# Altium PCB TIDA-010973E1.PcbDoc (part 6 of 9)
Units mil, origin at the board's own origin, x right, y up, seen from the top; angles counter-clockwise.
Board outline 5166 x 3669 mil, 8 copper layers (L01 - TOP, L02 - GND, L03 - SIG, L04 - GND, L05 - PWR, L06 - SIG, L07 - GND, L08 - BOTTOM), stack 61.7 mil thick; 677 components, 493 nets, 2522 pads, 1424 vias.
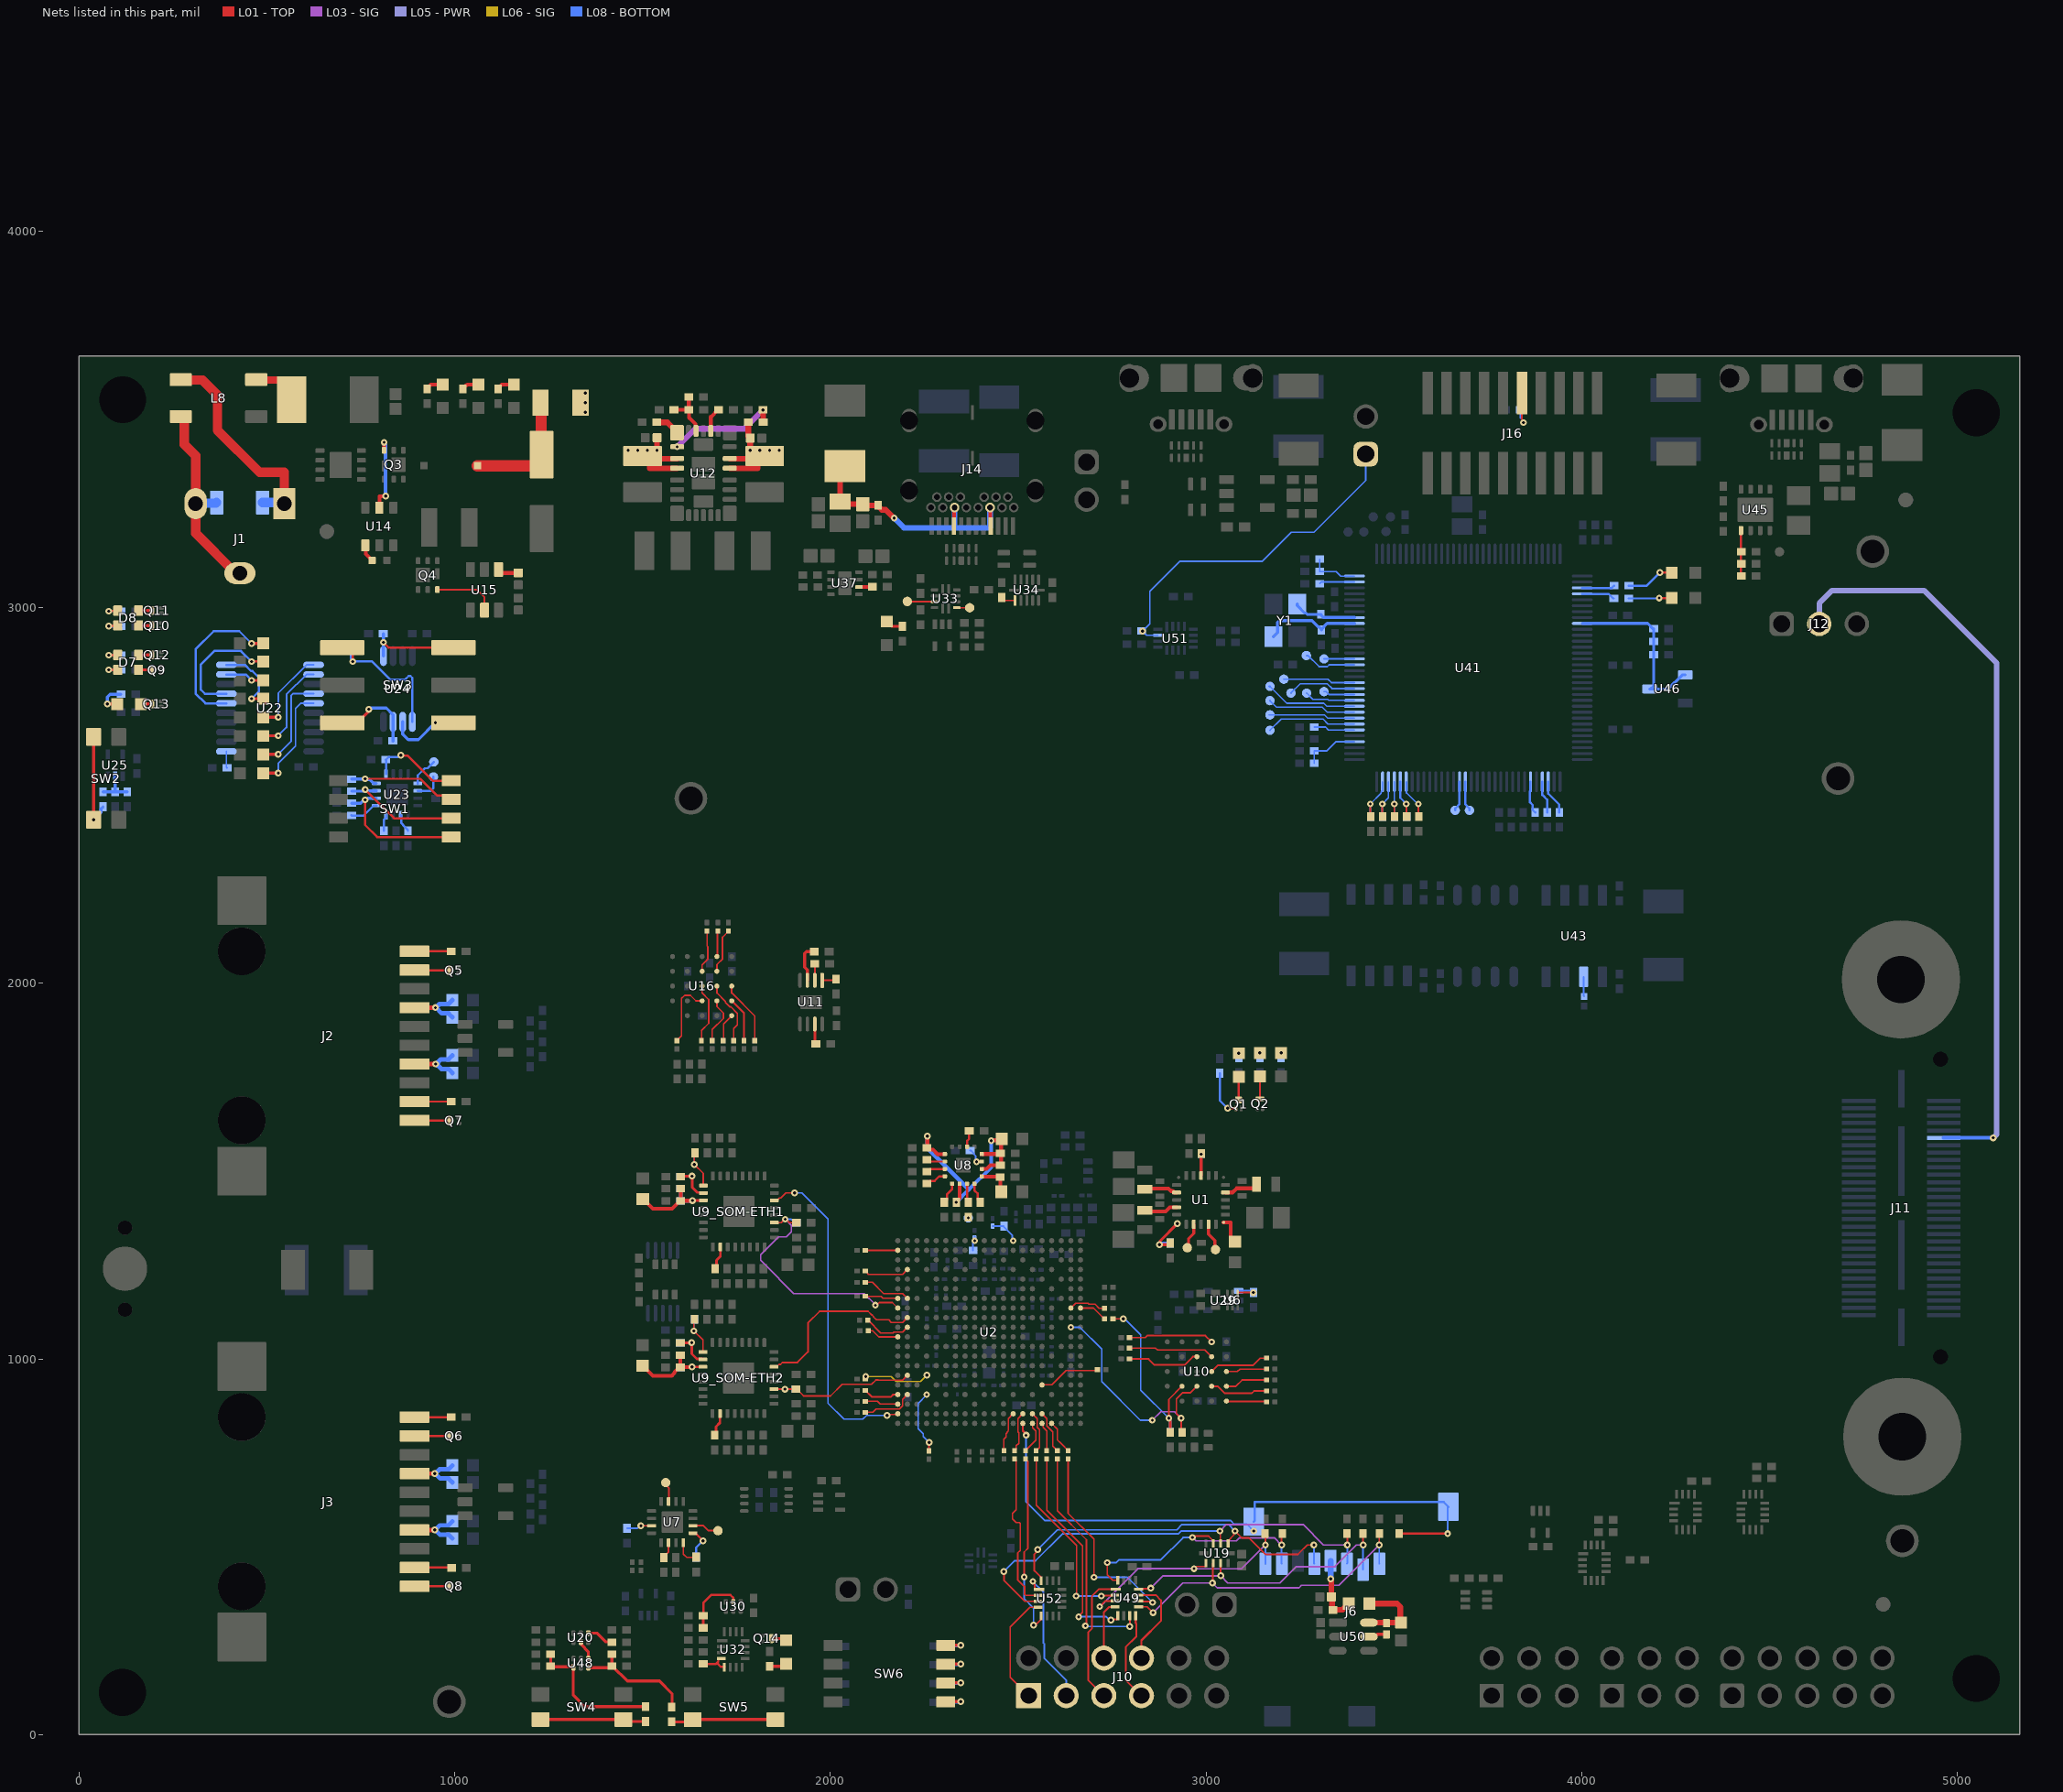
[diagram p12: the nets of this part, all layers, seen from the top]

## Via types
v1: diameter 18, hole 8, L01 - TOP to L08 - BOTTOM, tented both sides, 1389 vias
v2: diameter 19.68, hole 7.87, L01 - TOP to L08 - BOTTOM, 24 vias
v3: diameter 19.68, hole 7.87, L01 - TOP to L08 - BOTTOM, tented both sides, 11 vias

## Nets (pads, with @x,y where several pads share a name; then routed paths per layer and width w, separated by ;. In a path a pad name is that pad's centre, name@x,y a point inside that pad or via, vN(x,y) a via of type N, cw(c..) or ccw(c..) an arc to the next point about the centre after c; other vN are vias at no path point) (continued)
MMC0_CD: J6.9 R221.1 U2.A7 | length 1625.5
  L01 - TOP w6: U2.A7@2512.31,828.5 2512.31,808.93 2521,800.25 v1(2521,797) ; R221.1@3514,535.32 3514.16,535.16 3642.84,535.16 v1(3643,535)
  L08 - BOTTOM w4.5: v1(2521,797) 2521,620 2570.5,570.5 3064.41,570.5 3074.45,560.45 3108.55,560.45 v1(3127,542)
  L08 - BOTTOM w6: J6.9@3127.21,567.25 3129,569.04 3129,619 3632.54,619 J6.9@3644.92,606.62 3643,604.69 v1(3643,535)
MMC0_CLK: R183.2 U52.2 | length 427.4
  L01 - TOP w4.5: R183.2@2490.58,733.98 2494.63,729.93 2494.63,726.5 2494.63,599.03 2484.75,589.14 2484.75,574.86 2494.86,564.75 2502.86,564.75 2505.5,562.11 2505.5,490.35 2498.75,483.6 2498.75,412.85 2517.07,394.53 2517.07,373.51 2519.71,370.87 U52.2@2553.5,370.87
MMC0_CLK_CARD: J6.5 U19.1 U52.16 | length 984.1
  L01 - TOP w4.5: v1(2552,493) 2552,489.35 2543,480.35 2543,436.5 2561.38,418.12 U52.16@2561.38,410.24 ; U19.1@3058.53,509.57 3058.53,516.46 3074.42,532.35 3074.42,539.42 v1(3077,542) 3094.75,524.25 3113.93,524.25 3158,480.18 3244.57,480.18 3269.4,505 v1(3287,505)
  L08 - BOTTOM w4.5: v1(2552,493) 2604,545 2922,545 2936.25,559.25 3059.75,559.25 v1(3077,542) ; v1@3287,499 3287,456.27 J6.5@3288.23,455.04
MMC0_CLK_CON: J10.3 U52.1 | length 374.8
  L01 - TOP w4.3: v1(2539,408) 2539,404.29 2543.84,399.45 2543.84,388.41 2545.63,386.62 U52.1@2555.47,386.62
  L08 - BOTTOM w4.5: v1(2539,408) 2566.75,380.25 2566.75,244.25 2569.71,241.29 2569.71,203.29 2628,145.01 J10.3@2628,104
MMC0_CMD: R227.2 U52.5 | length 493.8
  L01 - TOP w4.3: 2516,486 2526,496 2526,727.19 2520,733.19 R227.2@2520,733.98
  L01 - TOP w4.5: v1(2516,420) 2516,486 ; v1(2541,292) 2543.58,294.58 2548.08,294.58 2561.38,307.88 U52.5@2561.38,315.76
  L08 - BOTTOM w4.5: v1(2516,420) 2516,362 2541,337 v1(2541,292)
MMC0_CMD_CARD: J6.3 R177.1 U19.2 U52.3 | length 1240.5
  L01 - TOP w4.5: v1(2462,434) 2462,411.1 2517.97,355.13 U52.3@2553.5,355.13 ; v1(3037,542) 3037.92,541.08 3037.92,510.5 U19.2@3038.84,509.57 ; R177.1@3375,535.32 3376,534.32 v1(3376,505)
  L03 - SIG w4.5: v1(3037,542) 3054.25,559.25 3258.42,559.25 3312.67,505 v1(3376,505)
  L08 - BOTTOM w4.5: v1(2462,434) 2491,463 2546.39,463 2617.89,534.5 2926.35,534.5 2934.1,542.25 3036.75,542.25 v1(3037,542) ; J6.3@3374.84,455.04 3376,456.2 v1(3376,505)
MMC0_CMD_CON: J10.1 U52.4 | length 299.5
  L01 - TOP w4.5: J10.1@2528,104 2479,153 2479,287 2531.38,339.38 U52.4@2553.5,339.38
MMC0_D0: R228.2 U49.2 | length 515
  L01 - TOP w4.3: R228.2@2548,733.98 2548,611.02 2655.75,503.27 2655.75,370.75 v1(2654,369) ; v1(2721,369) 2722.44,370.44 2756.07,370.44 U49.2@2757.5,371.87
  L08 - BOTTOM w4.3: v1(2654,369) v1(2721,369)
MMC0_D0_CARD: J6.7 R178.1 U19.3 U49.16 | length 723.3
  L01 - TOP w4.5: v1(2737,458) 2737,426 2751.76,411.24 U49.16@2765.38,411.24 ; v1(2964,525) 2967.65,525 2971.3,528.65 3006.97,528.65 3019.16,516.46 U19.3@3019.16,509.57 ; v1(3201,505) 3201,533.32 R178.1@3203,535.32
  L03 - SIG w4.5: v1(2964,525) 2964.39,525 2973.39,516 3080.6,516 3088.85,524.25 3181.42,524.25 3200.67,505 v1(3201,505)
  L08 - BOTTOM w4.5: v1(2737,458) 2760.6,458 2767.6,465 2879,465 2939,525 v1(2964,525) ; v1(3201,505) 3201,455.66 J6.7@3201.62,455.04
MMC0_D0_CON: J10.5 U49.1 | length 359.5
  L01 - TOP w4.3: J10.5@2728,104 2686.39,145.61 2686.39,272.7 2696.15,282.47 2696.15,368.4 2715.37,387.62 U49.1@2759.47,387.62 U49.1@2757.69,389.41
MMC0_D1: R229.2 U49.5 | length 581.3
  L01 - TOP w4.3: R229.2@2576.03,733.98 2576.03,597.55 2671.3,502.29 2671.3,325.55 2661,315.25 v1(2661,314) ; v1(2747,305) 2749.09,307.09 2763.59,307.09 2765.38,308.88 U49.5@2765.38,316.76
  L08 - BOTTOM w4.3: v1(2661,314) 2734.29,314 2743.29,305 v1(2747,305)
MMC0_D1_CARD: J6.8 R179.1 U19.6 U49.3 | length 678.4
  L01 - TOP w4.5: v1(2717,341) 2717.4,341 2732.52,356.13 U49.3@2757.5,356.13 ; v1(2968,442) 2973.85,447.85 2997.79,447.85 2999.47,449.54 U19.6@2999.47,456.43 ; R179.1@3157,535.32 3158,534.32 v1(3158,505)
  L03 - SIG w4.5: v1(2717,341) 2717.4,341 2818.4,442 2967.5,442 2968,441.5 3094.5,441.5 v1(3158,505)
  L08 - BOTTOM w4.3: J6.8@3158,455.35 v1(3158,505)
  L08 - BOTTOM w5: J6.8@3158,455.35 J6.8@3158.31,455.04
MMC0_D1_CON: J10.6 U49.4 | length 157.5
  L01 - TOP w5: J10.6@2728,204 2728,326 2741.76,339.76 2756.89,339.76 U49.4@2757.5,340.38
MMC0_D2: R230.2 U49.7 | length 624.7
  L01 - TOP w4.3: R230.2@2604.52,733.98 2604.52,596.06 2681.6,518.98 2681.6,292.6 v1(2679,290)
  L01 - TOP w5: U49.7@2796.87,316.76 2796.94,316.69 2796.94,288.06 v1(2797,288)
  L08 - BOTTOM w4.3: v1(2679,290) 2681.15,287.85 2796.85,287.85 v1(2797,288)
MMC0_D2_CARD: J6.1 R175.1 U19.7 U49.9 | length 866.2
  L01 - TOP w4.3: U49.9@2820.5,340.38 2820.81,340.69 2843.31,340.69 v1(2859,325)
  L01 - TOP w4.5: v1(3017,404) 3018.08,405.08 3018.08,455.35 U19.7@3019.16,456.43 ; v1(3461,505) R175.1@3461,535.32
  L03 - SIG w4.5: v1(2859,325) 2938,404 v1(3017,404) 3030,391 3247.25,391 3254,397.75 3353.75,397.75 v1(3461,505)
  L08 - BOTTOM w4.5: v1(3461,505) 3461,455.5 J6.1@3461.46,455.04
MMC0_D2_CON: J10.7 U49.8 | length 242.7
  L01 - TOP w5: U49.8@2812.62,316.76 2812.62,297.13 2814.5,295.25 2814.5,261.5 2786.04,233.04 2786.04,145.96 J10.7@2828,104
MMC0_D3: R231.2 U49.10 | length 566.6
  L01 - TOP w4.3: R231.2@2633,733.98 2633,589.47 2702,520.47 v1(2702,419) ; U49.10@2820.5,356.13 2822.28,354.34 2855.66,354.34 v1(2858,352)
  L08 - BOTTOM w4.3: v1(2702,419) 2702.15,419.15 2790.85,419.15 v1(2858,352)
MMC0_D3_CARD: J6.2 R176.1 U19.8 U49.12 | length 791.4
  L01 - TOP w4.3: U49.12@2820.5,387.62 2821.69,388.81 2851.81,388.81 v1(2853,390)
  L01 - TOP w4.5: U19.8@3038.84,456.43 3038.92,456.35 3038.92,423.08 v1(3039,423) ; v1(3418,505) R176.1@3418,535.32
  L03 - SIG w4.5: v1(2853,390) 2886,423 v1(3039,423) 3058,404 3196.5,404 3240,447.5 3342.9,447.5 3400.4,505 v1(3418,505)
  L08 - BOTTOM w4.5: v1(3418,505) 3418,439.45 J6.2@3418.15,439.3
MMC0_D3_CON: J10.8 U49.11 | length 240.8
  L01 - TOP w5: U49.11@2820.5,371.87 2866.13,371.87 2880,358 2880,303 2828,251 J10.8@2828,204
MRn_CLK_SOM-ETH1: R206_SOM-ETH1.1 R207_SOM-ETH1.2 U2.N20 U9_SOM-ETH1.19 | length 686.3
  L01 - TOP w4.3: U9_SOM-ETH1.19@1851.13,1362.95 1851.29,1362.8 1869.39,1362.8 1878.6,1372 v1(1880,1372) 1882.11,1372 1891.47,1362.64 R207_SOM-ETH1.2@1909.73,1362.64 ; v1(2120,1143) 2123.71,1143 2130.76,1150.05 2165.18,1150.05 U2.N20@2179.64,1135.59
  L03 - SIG w4.3: v1(1880,1372) 1896.15,1355.85 1896.15,1337.9 1883.25,1325 1862.75,1325 1814.85,1277.1 1814.85,1262.9 1863.44,1214.31 1863.44,1213.05 1902.49,1174 2090.25,1174 2120,1144.25 v1(2120,1143)
  L08 - BOTTOM w4.3: v1(1880,1372) 1895.45,1372 1897.12,1370.33 1902.04,1370.33 R206_SOM-ETH1.1@1909.73,1362.64
MRn_CLK_SOM-ETH2: R206_SOM-ETH2.1 R207_SOM-ETH2.2 U2.F19 U9_SOM-ETH2.19 | length 415.1
  L01 - TOP w3.5: 2127.47,943.88 2192.65,943.88 U2.F19@2205.23,956.46
  L01 - TOP w4.3: U9_SOM-ETH2.19@1850.13,919.95 1850.29,919.8 1878.98,919.8 v1(1879.13,919.64) R207_SOM-ETH2.2@1908.73,919.64 1910.7,919.64 1928.85,901.49 2000.49,901.49 2031.55,932.55 2109.81,932.55 2121.14,943.88 2127.47,943.88
  L08 - BOTTOM w4.3: v1(1879.13,919.64) R206_SOM-ETH2.1@1908.73,919.64
MTn_CLK_SOM-ETH1: U2.B20 U9_SOM-ETH1.22 | length 879.5
  L01 - TOP w4.3: U9_SOM-ETH1.22@1851.13,1422.01 1858.02,1422.01 1864.64,1428.62 1868.86,1428.62 1882.09,1441.85 1904.85,1441.85 v1(1905,1442) ; v1(2151,850) 2153.28,852.28 2177.82,852.28 U2.B20@2179.64,854.09
  L08 - BOTTOM w4.3: v1(1905,1442) 1924.69,1442 1994,1372.69 1994,882 2036.15,839.85 2086.65,839.85 2096.8,850 v1(2151,850)
MTn_CLK_SOM-ETH2: U2.M19 U9_SOM-ETH2.22 | length 479.5
  L01 - TOP w3.5: 2123.02,1104.35 2127.47,1104.35 2155.65,1104.35 2162.58,1097.42 2192.65,1097.42 U2.M19@2205.23,1110
  L01 - TOP w4.3: U9_SOM-ETH2.22@1850.13,979.01 1857.02,979.01 1863.64,985.62 1867.86,985.62 1872.88,990.64 1912.64,990.64 1940.68,1018.68 1940.68,1096.12 1971.57,1127 2088.75,1127 2088.9,1126.85 2100.52,1126.85 2109.92,1117.45 2110.49,1117.45 2115.26,1112.68 2115.26,1112.11 2123.02,1104.35
NetC44_1: C44.1 U1.7 | length 75.6
  L01 - TOP w10: U1.7@3046.56,1363.62 3064.76,1363.62 3065.4,1362.98 3065.4,1322.7 3076.15,1311.95 C44.1@3077.13,1311.95
NetC46_1: C46.1 J1.2 J1.3 L8.4 | length 570.3
  L01 - TOP w25: L8.4@271.61,3507.79 276.77,3507.79 281,3503.56 281,3434 311,3404 J1.2@311,3276 311,3197.26 417.3,3090.96 J1.3@429.11,3090.96
  L08 - BOTTOM w25: J1.2@311,3297.03 J1.2@311,3276 312.5,3277.5 365.48,3277.5 C46.1@366.98,3279
NetC46_2: C46.2 J1.1 L8.5 | length 576
  L01 - TOP w25: L8.5@271.61,3606.21 272.82,3605 330,3605 369,3566 369,3472 481.22,3359.78 547.22,3359.78 J1.1@547.22,3276
  L08 - BOTTOM w25: C46.2@489.02,3279 544.22,3279 J1.1@547.22,3276
NetC64_1: C64.1 C65.1 C66.1 C67.1 L17.2 U8.5 U8.10 U8.14 U8.16 | length 728.6
  L01 - TOP w10: C65.1@2257.4,1561.91 2262.24,1557.07 2273.21,1557.07 2286.37,1543.91 2287.15,1544.69 2304.39,1544.69 U8.5@2304.8,1545.1 ; v1(2335.23,1416.87) 2335.23,1418.83 2344.17,1427.78 U8.10@2344.17,1466.36 ; U8.14@2403.23,1505.73 2403.64,1506.15 2415.83,1506.15 2425.72,1516.03 C67.1@2452.53,1516.03 ; U8.16@2403.23,1545.1 2403.64,1545.52 C64.1@2450.52,1545.52
  L01 - TOP w12: C65.1@2257.4,1561.91 2258.37,1562.88 v1(2258.37,1592.88) ; v1(2428.37,1580.91) 2429.52,1582.06 2452.61,1582.06 L17.2@2454.5,1583.94 ; C67.1@2452.53,1516.03 2454.5,1518 C64.1@2454.5,1545.56 ; C64.1@2454.5,1547.53 L17.2@2454.5,1583.94 ; L17.2@2456.46,1585.91 L17.2@2454.5,1583.94
  L08 - BOTTOM w10: v1(2335.23,1416.87) 2368.98,1450.61 2428.37,1510.01 v1(2428.37,1580.91)
  L08 - BOTTOM w12: v1(2258.37,1592.88) 2258.37,1561.22 2368.98,1450.61
NetC68_2: C68.2 L18.2 U8.13 | length 90.2
  L01 - TOP w10: U8.13@2403.23,1486.05 2403.64,1485.63 2450.82,1485.63 C68.2@2452.25,1484.2 2452.25,1448.39 L18.2@2455.48,1445.17
NetC73_SOM-ETH1_1: C73_SOM-ETH1.1 C74_SOM-ETH1.1 C75_SOM-ETH1.1 C76_SOM-ETH1.1 L5_SOM-ETH1.1 U9_SOM-ETH1.3 | length 278.2
  L01 - TOP w7: v1(1633.13,1421.64) 1633.32,1421.82 1661.97,1421.82 U9_SOM-ETH1.3@1662.16,1422.01 U9_SOM-ETH1.3@1661.34,1422.82
  L01 - TOP w10: L5_SOM-ETH1.1@1501.26,1425.09 1502.24,1425.09 1527.5,1399.84 1579.01,1399.84 1599.85,1420.68 C74_SOM-ETH1.1@1601.82,1420.68 ; C74_SOM-ETH1.1@1601.82,1422.65 C73_SOM-ETH1.1@1601.82,1453.16 C73_SOM-ETH1.1@1603.79,1453.16 ; C74_SOM-ETH1.1@1601.83,1421.16 1632.65,1421.16 v1(1633.13,1421.64)
  L08 - BOTTOM w10: C76_SOM-ETH1.1@1601.82,1453.16 C75_SOM-ETH1.1@1601.82,1420.68 1602.3,1421.16 1632.65,1421.16 v1(1633.13,1421.64)
NetC73_SOM-ETH2_1: C73_SOM-ETH2.1 C74_SOM-ETH2.1 C75_SOM-ETH2.1 C76_SOM-ETH2.1 L5_SOM-ETH2.1 U9_SOM-ETH2.3 | length 281
  L01 - TOP w7: v1(1632.13,978.64) 1632.32,978.82 1660.97,978.82 U9_SOM-ETH2.3@1661.16,979.01 U9_SOM-ETH2.3@1660.34,979.82
  L01 - TOP w10: L5_SOM-ETH2.1@1500.26,982.09 1501.24,982.09 1527.79,955.55 1578.35,955.55 1585.54,962.75 1585.54,964.37 1600.82,979.65 C73_SOM-ETH2.1@1600.82,1010.16 C73_SOM-ETH2.1@1602.79,1010.16 ; C74_SOM-ETH2.1@1600.83,978.16 1631.65,978.16 v1(1632.13,978.64)
  L08 - BOTTOM w10: C76_SOM-ETH2.1@1600.82,1010.16 C75_SOM-ETH2.1@1600.82,977.68 1601.3,978.16 1631.65,978.16 v1(1632.13,978.64)
NetC81_SOM-ETH1_2: C81_SOM-ETH1.2 C191_SOM-ETH1.1 U9_SOM-ETH1.2 | length 127.8
  L01 - TOP w7: C81_SOM-ETH1.2@1601.82,1485.64 1602.33,1486.15 1631.75,1486.15 v1(1632.26,1486.65) 1632.26,1456.65 1645.8,1443.11 1660.74,1443.11 U9_SOM-ETH1.2@1662.16,1441.69
  L08 - BOTTOM w7: C191_SOM-ETH1.1@1601.82,1485.64 1602.33,1486.15 1631.75,1486.15 v1(1632.26,1486.65)
NetC81_SOM-ETH2_2: C81_SOM-ETH2.2 C191_SOM-ETH2.1 U9_SOM-ETH2.2 | length 127.8
  L01 - TOP w7: C81_SOM-ETH2.2@1600.82,1042.64 1601.33,1043.15 1630.75,1043.15 v1(1631.26,1043.65) 1631.26,1013.65 1644.8,1000.11 1659.74,1000.11 U9_SOM-ETH2.2@1661.16,998.69
  L08 - BOTTOM w7: C191_SOM-ETH2.1@1600.82,1042.64 1601.33,1043.15 1630.75,1043.15 v1(1631.26,1043.65)
NetC87_1: C87.1 U12.23 | length 65.5
  L01 - TOP w10: U12.23@1682.09,3469.86 1682.09,3506.99 1700.76,3525.65 C87.1@1702.72,3525.65
NetC91_1: C91.1 L6.2 L7.1 | length 330.8
  L01 - TOP w30: L6.2@1060.87,3377 1215.5,3377 1232,3393.5 C91.1@1232,3406.43 1230.43,3408 1230.43,3543.43 L7.1@1228.85,3545
NetC92_2: C92.2 C93.2 C94.2 C95.2 L7.2 R58.2 U12.3 U12.4 U12.18 U12.19 | length 503.5
  L01 - TOP w15: v1(1513.33,3418) 1519.79,3411.55 1519.79,3370.45 U12.4@1592.53,3370.45 ; C93.2@1539.16,3451.65 1539.16,3418.16 v1(1539,3418) 1539,3401.25 1544.21,3396.04 U12.3@1592.53,3396.04 ; U12.18@1732.29,3370.45 1806.21,3370.45 1806.21,3411.55 v1(1812.67,3418) ; U12.19@1732.29,3396.04 1781.61,3396.04 1787,3401.43 v1(1787,3418) 1786.65,3418.35 C92.2@1786.65,3450.65 1782.04,3455.28 R58.2@1782.04,3492.65
  other v1: 1462,3418 1487.67,3418 1838.33,3418 1864,3418 1348,3519 1348,3544.67 1348,3570.33
NetC98_2: C98.2 U14.1 | length 47.3
  L01 - TOP w10: U14.1@762.6,3165.12 764.14,3163.57 764.14,3141.8 C98.2@780.63,3125.31
NetC99_2: C99.2 R60.1 R62.2 U12.25 | length 137.8
  L01 - TOP w10: R60.1@1584.09,3525.65 R62.2@1623.72,3525.65 ; C99.2@1623.31,3560 1623.52,3559.8 1623.52,3525.86 R62.2@1623.72,3525.65 ; U12.25@1642.72,3469.86 1640.93,3471.65 1640.93,3487.86 1624,3504.79 1624,3525.38 R62.2@1623.72,3525.65
NetC101_2: C101.2 U15.1 | length 58
  L01 - TOP w10: U15.1@1117.09,3101.13 1117.09,3098.57 1123.9,3091.76 C101.2@1169.68,3091.76
NetC102_1: C102.1 C104.1 J2.4 | length 163.2
  L01 - TOP w12: J2.4@893.84,1935 v1(949,1935)
  L08 - BOTTOM w12: v1(949,1935) v1@950.62,1935 ; C104.1@993.79,1909 993.79,1909.98 984.04,1919.73 965.89,1919.73 v1@950.62,1935 ; C102.1@993.79,1955 993.79,1954.16 984.04,1944.42 960.04,1944.42 v1@950.62,1935
NetC103_1: C103.1 C105.1 J3.4 | length 165.2
  L01 - TOP w12: J3.4@893.84,695 v1(947,695)
  L08 - BOTTOM w12: v1(947,695) v1@948.62,695 ; C105.1@993.79,671 993.79,671.98 984.04,681.73 961.89,681.73 v1@948.62,695 ; C103.1@993.79,717 993.79,716.16 984.04,706.42 960.04,706.42 v1@948.62,695
NetC106_1: C106.1 C108.1 J2.7 | length 162.7
  L01 - TOP w12: J2.7@893.84,1785 v1(950,1785)
  L08 - BOTTOM w12: v1(950,1785) v1@951.62,1785 ; C108.1@993.79,1761 993.79,1761.98 984.04,1771.73 964.89,1771.73 v1@951.62,1785 ; C106.1@993.79,1808 993.79,1807.02 984.04,1797.27 963.89,1797.27 v1@951.62,1785
NetC107_1: C107.1 C109.1 J3.7 | length 165.3
  L01 - TOP w12: J3.7@893.84,545 v1(947,545)
  L08 - BOTTOM w12: v1(947,545) v1@948.62,545 ; C109.1@993.79,522 993.79,522.98 984.04,532.73 960.89,532.73 v1@948.62,545 ; C107.1@993.79,568 993.79,567.02 984.04,557.27 960.89,557.27 v1@948.62,545
NetC113_1: C113.1 U23.14 | length 49.2
  L08 - BOTTOM w6: U23.14@856.96,2447.04 858.69,2445.32 858.69,2426.23 862.84,2422.07 862.84,2420.81 876,2407.65 C113.1@876,2405.68
NetC114_1: C114.1 R12.1 R98.2 U25.2 | length 106
  L08 - BOTTOM w8: R98.2@64.81,2508.91 R12.1@96.81,2508.91 ; U25.2@97,2550.87 96.91,2550.77 96.91,2509 R12.1@96.81,2508.91 ; C114.1@128.81,2508.91 R12.1@96.81,2508.91
NetC121_2: C121.2 U7.14 | length 44.3
  L01 - TOP w4.5: C121.2@1557,471.69 1557,473.65 1569.63,486.28 U7.14@1569.63,510.76
NetC122_1: C122.1 R122.2 U30.2 | length 169.5
  L01 - TOP w6: R122.2@1661.92,316.46 1662,316.54 1662,351 1683,372 1734.35,372 1741.86,364.49 U30.2@1741.86,353.28
  L01 - TOP w8: C122.1@1661.92,284.46 R122.2@1661.92,316.46
NetC125_2: C125.2 C127.1 D18.2 J14.A4 J14.A9 J14.B4 J14.B9 L9.1 | length 736.8
  L01 - TOP w10: J14.A9@2328.79,3216.64 2329.69,3217.54 2329.69,3264.79 J14.B4@2330.76,3265.85 ; J14.B9@2425.24,3265.85 2426.31,3264.79 2426.31,3217.54 J14.A4@2427.21,3216.64
  L01 - TOP w15: D18.2@2039.32,3375.99 2026.32,3362.99 L9.1@2026.32,3281.53 2033.17,3274.67 C125.2@2086.32,3274.67 2089.3,3271.69 C127.1@2127.32,3271.69 2127.32,3269.72 2137.24,3259.79 2147.4,3259.79 2169.19,3238 v1(2170,3238)
  L08 - BOTTOM w15: v1(2170,3238) 2196.2,3211.8 2329.24,3211.8 ; J14.B4@2330.76,3265.85 2330.76,3213.32 2329.24,3211.8 ; J14.B9@2425.24,3265.85 2425.24,3213.24 2423.8,3211.8 2329.24,3211.8
NetC134_2: C134.2 U37.6 | length 36.1
  L01 - TOP w10: U37.6@2076.4,3054.44 2076.48,3054.52 2111.83,3054.52 C134.2@2112.31,3055
NetC139_1: C139.1 R146.1 U41.96 | length 130.2
  L08 - BOTTOM w4.3: C139.1@3302.35,3128.35 R146.1@3302.35,3095.85 3302.71,3095.5 3346.5,3095.5 3358.61,3083.39 U41.96@3394.86,3083.39
NetC152_2: C152.2 R163.2 U41.68 | length 150
  L08 - BOTTOM w4.3: R163.2@3288,2585 C152.2@3288,2618 3321,2618 3345.45,2642.45 U41.68@3394.86,2642.45
NetC159_1: C159.1 U41.88 Y1.1 | length 267
  L08 - BOTTOM w8: Y1.1@3179.51,2921.99 3190.69,2933.16 3190.69,2960.31 3195.37,2965 3281.99,2965 3299.2,2947.8 3301.17,2947.8 C159.1@3307.01,2941.95 ; C159.1@3307.01,2939.98 C159.1@3307.01,2941.95 ; U41.88@3394.86,2957.41 3322.47,2957.41 C159.1@3307.01,2941.95
NetC160_1: C160.1 U41.89 Y1.3 | length 170.5
  L08 - BOTTOM w8: Y1.3@3242.51,3008.61 3242.51,3004.67 3262.13,2985.05 3266.07,2985.05 3269.5,2981.61 C160.1@3306.01,2981.61 3306.01,2979.65 3312.5,2973.16 U41.89@3394.86,2973.16
NetC161_2: C161.2 R166.1 R168.2 U45.5 | length 120.8
  L01 - TOP w6: U45.5@4423.61,3204.52 4423.61,3084.7 R168.2@4424.31,3084
NetC164_1: C164.1 C165.1 R165.1 U41.9 U46.1 U46.3 | length 469.7
  L08 - BOTTOM w8: U41.9@4001.16,2957.41 4175.49,2957.41 4189.35,2943.55 R165.1@4191.31,2943.55 C165.1@4191.31,2909 C164.1@4191.31,2874.55 4191.31,2790.81 U46.3@4183.5,2783 ; U46.3@4180.76,2783 U46.3@4183.5,2783 ; U46.1@4275.24,2820.4 4267.37,2820.4 4229.97,2783 U46.3@4183.5,2783
NetC179_2: C179.2 C182.1 J6.4 L16.1 | length 182.8
  L01 - TOP w15: v1(3332,415) 3332,414.19 3333.31,412.87 C182.1@3333.31,367 3335.5,364.81 3335.5,334.19 C179.2@3337.69,332 3338.25,332.57 3363.99,332.57 3379.44,348.02 L16.1@3379.44,349
  L08 - BOTTOM w15: J6.4@3331.54,462.92 3331.77,462.69 3331.77,415.23 v1(3332,415)
NetC181_2: C181.2 L16.2 R222.2 U50.6 | length 215.7
  L01 - TOP w15: U50.6@3433.36,298.4 U50.6@3433.5,298.55 ; U50.6@3433.96,299 U50.6@3433.5,298.55 ; L16.2@3433.96,348.4 L16.2@3434.56,349 3508.21,349 3517,340.21 3517,300.69 C181.2@3519,298.69 3518.86,298.55 U50.6@3433.5,298.55
NetC194_1: C194.1 R112.2 R171.1 U48.1 | length 373.2
  L01 - TOP w8: C194.1@1255.92,214.46 R171.1@1255.92,182.46 1257.33,181.05 1315.14,181.05 U48.1@1316.55,179.64 1316,179.09 1316,105 1346.31,74.69 R112.2@1508,74.69
NetC195_1: C195.1 R113.2 R173.1 U48.3 | length 322.8
  L01 - TOP w8: U48.3@1355.92,178.65 1414.74,178.65 R173.1@1418.55,182.46 ; C195.1@1418.55,214.46 R173.1@1418.55,182.46 ; R113.2@1578,73.69 1579,74.69 1579,109 1545.19,142.81 1460.17,142.81 1420.52,182.46 R173.1@1418.55,182.46
NetC212_1: C212.1 C213.2 U2.Y8 | length 78.7
  L08 - BOTTOM w4.5: C213.2@2432.15,1353.47 2461.82,1353.47 2461.82,1352.15 2484.14,1329.83 2484.14,1317.31 v1(2486.72,1314.72)
NetC214_1: C214.1 C215.2 U2.Y12 | length 38.5
  L08 - BOTTOM w5: C214.1@2379.83,1289.13 2379.83,1316.16 2384.32,1320.64 C215.2@2384.32,1325.82
  other v1: 2384.36,1314.72
NetD1_2: D1.2 R3.2 | length 12.8
  L08 - BOTTOM w5: R3.2@3200,1801.69 v1(3200,1814.5)
NetD2_1: D2.1 Q1.3 | length 61.4
  L01 - TOP w6: Q1.3@3086.5,1689.33 3086.5,1750 D2.1@3087,1750.5
NetD2_2: D2.2 R4.1 | length 11.8
  L08 - BOTTOM w5: R4.1@3087,1801.68 v1(3087,1813.5)
NetD3_1: D3.1 Q2.3 | length 60
  L01 - TOP w6: D3.1@3143,1751.58 3143.5,1751.08 Q2.3@3143.5,1691.8
NetD3_2: D3.2 R5.1 | length 13.1
  L08 - BOTTOM w5: v1(3143,1814.57) 3143,1802.18 R5.1@3143.5,1801.68
NetD4_2: D4.2 R63.1 | length 48
  L01 - TOP w10: R63.1@1022,3581.68 1022,3583.65 1029.34,3591 1031.31,3591 1033.81,3593.5 D4.2@1064,3593.5
NetD5_2: D5.2 R64.1 | length 48
  L01 - TOP w10: R64.1@927,3581.69 927,3583.65 936.84,3593.5 D5.2@969,3593.5
NetD6_2: D6.2 R65.1 | length 48
  L01 - TOP w10: R65.1@1116,3581.69 1116,3583.65 1125.84,3593.5 D6.2@1158,3593.5
NetD7_1: D7.1 Q9.3 | length 35.7
  L01 - TOP w8: D7.1@158.87,2834 159.03,2833.84 194.26,2833.84 Q9.3@194.42,2833.69
NetD7_2: D7.2 Q12.3 | length 35.7
  L01 - TOP w8: D7.2@158.87,2873.37 159.03,2873.53 194.26,2873.53 Q12.3@194.42,2873.69
NetD7_3: D7.3 R94.2 | length 56.4
  L01 - TOP w8: v1(80,2873) 80.18,2873.19 103.57,2873.19 D7.3@103.76,2873.37
  L08 - BOTTOM w8: v1(80,2873) 80.18,2873.19 112.13,2873.19 R94.2@112.31,2873.37
NetD7_4: D7.4 R92.2 | length 56.1
  L01 - TOP w8: v1(80,2834) D7.4@103.76,2834
  L08 - BOTTOM w8: v1(80,2834) R92.2@112.31,2834
NetD8_1: D8.1 Q10.3 | length 35.7
  L01 - TOP w8: D8.1@158.87,2952 159.03,2951.84 194.26,2951.84 Q10.3@194.42,2951.69
NetD8_2: D8.2 Q11.3 | length 35.7
  L01 - TOP w8: D8.2@158.87,2991.37 159.03,2991.53 194.26,2991.53 Q11.3@194.42,2991.69
NetD8_3: D8.3 R91.2 | length 57.6
  L01 - TOP w6: v1(80,2990) 102.39,2990 D8.3@103.76,2991.37
  L08 - BOTTOM w6: v1(80,2990) R91.2@112.31,2990 R91.2@113.31,2990
NetD8_4: D8.4 R90.2 | length 54.9
  L01 - TOP w8: v1@81,2950 82,2951 102.76,2951 D8.4@103.76,2952
  L08 - BOTTOM w8: v1@81,2950 R90.2@112.31,2950
  other v1: 80,2950
NetD10_1: D10.1 U22.6 | length 425.8
  L01 - TOP w8: v1(460,2904) 490.44,2904 D10.1@491.43,2904.99 D10.1@491.95,2905.51
  L08 - BOTTOM w6: U22.6@392.8,2744.83 337.17,2744.83 311,2771 311,2889 359,2937 427,2937 v1(460,2904)
NetD11_1: D11.1 U22.7 | length 333.6
  L01 - TOP w6: v1(460,2856) 491.01,2856 D11.1@491.43,2855.57 D11.1@491.95,2856.09
  L08 - BOTTOM w6: U22.7@392.8,2770.42 335.58,2770.42 325,2781 325,2848.49 360.88,2884.37 431.63,2884.37 v1(460,2856)
NetD12_1: D12.1 U22.9 | length 105.9
  L01 - TOP w8: v1(460,2806) 491.28,2806 D12.1@491.43,2806.16 D12.1@491.95,2806.67
  L08 - BOTTOM w6: U22.9@392.8,2821.6 444.4,2821.6 v1(460,2806)
NetD13_1: D13.1 U22.10 | length 197
  L01 - TOP w8: v1(460,2757) 491.17,2757 D13.1@491.43,2756.74 D13.1@491.95,2757.26
  L08 - BOTTOM w6: U22.10@392.8,2847.19 441.94,2847.19 458.6,2830.53 462.34,2830.53 479,2813.87 479,2776 v1(460,2757)
NetD14_1: D14.1 U22.11 | length 229
  L01 - TOP w8: D14.1@491.43,2707.32 491.95,2707.84 530.84,2707.84 v1(531,2708)
  L08 - BOTTOM w4.5: v1(531,2708) 531,2771.81 606.38,2847.19 U22.11@625.08,2847.19
NetD15_1: D15.1 U22.12 | length 252.8
  L01 - TOP w8: D15.1@491.43,2657.9 491.95,2658.42 530.84,2658.42 v1(531,2658.58)
  L08 - BOTTOM w4.5: v1(531,2658.58) 553,2680.58 553,2768.22 606.38,2821.6 U22.12@625.08,2821.6
NetD16_1: D16.1 U22.14 | length 272.3
  L01 - TOP w8: D16.1@491.43,2608.48 492.11,2609.16 v1(531,2609.16)
  L08 - BOTTOM w4.5: v1(531,2609.16) 565,2643.16 565,2765.38 570.05,2770.42 U22.14@625.08,2770.42
NetD17_1: D17.1 U22.15 | length 284.3
  L01 - TOP w8: D17.1@491.43,2559.06 491.53,2559.16 v1(531,2559.16)
  L08 - BOTTOM w4.5: v1(531,2559.16) 531,2584.77 577,2630.77 577,2731.06 590.77,2744.83 U22.15@625.08,2744.83
NetD19_1: D19.1 R143.2 | length 47.3
  L01 - TOP w8: D19.1@2150.28,2962.5 2163.09,2949.69 R143.2@2192.28,2949.69
NetD20_2: D20.2 R149.1 | length 115.2
  L01 - TOP w6: v1(4206,3025) D20.2@4239.5,3025
  L08 - BOTTOM w6: R149.1@4124.69,3024 4205,3024 v1(4206,3025)
NetD21_2: D21.2 R150.1 | length 130
  L01 - TOP w6: v1(4208,3093) 4239.5,3093 D21.2@4240.5,3092
  L08 - BOTTOM w6: R150.1@4125.37,3058 4173,3058 v1(4208,3093)
NetD23_1: D23.1 Q13.3 | length 29.2
  L01 - TOP w8: D23.1@164.99,2743 Q13.3@194.2,2743
NetD23_2: D23.2 R89.1 | length 84.2
  L01 - TOP w8: v1(76,2743) D23.2@102,2743
  L08 - BOTTOM w8: v1(76,2743) 76,2762 82.94,2768.94 R89.1@112.31,2768.94
NetD24_1: D24.1 Q14.3 | length 40.1
  L01 - TOP w8: Q14.3@1843.8,256 1877.5,256 D24.1@1882,251.5
NetD24_2: D24.2 R216.1 | length 45.6
  L01 - TOP w8: R216.1@1839,182.32 1875.81,182.32 D24.2@1882,188.5
NetF1_2: F1.2 L8.1 | length 166.5
  L01 - TOP w20: L8.1@472.39,3606.21 473.6,3605.01 537.76,3605.01 566.35,3576.43 F1.2@566.35,3553 F1.2@540.35,3579
NetJ2_1: J2.1 R84.1 | length 97.5
  L01 - TOP w6: J2.1@893.84,2085 R84.1@991.32,2085
NetJ2_2: J2.2 Q5.3 | length 89.8
  L01 - TOP w6: J2.2@893.84,2035 894.84,2034 Q5.3@983.2,2034
NetJ2_9: J2.9 R86.1 | length 97.5
  L01 - TOP w6: J2.9@893.84,1685 R86.1@991.32,1685
NetJ2_10: J2.10 Q7.3 | length 92.8
  L01 - TOP w6: J2.10@893.84,1635 894.84,1634 Q7.3@986.2,1634
NetJ3_1: J3.1 R85.1 | length 97.5
  L01 - TOP w6: J3.1@893.84,845 R85.1@991.32,845
NetJ3_2: J3.2 Q6.3 | length 91.6
  L01 - TOP w6: J3.2@893.84,795 Q6.3@985.43,795
NetJ3_9: J3.9 R87.1 | length 98.9
  L01 - TOP w6: J3.9@893.84,445 991.32,445 R87.1@992.32,444
NetJ3_10: J3.10 Q8.3 | length 91.6
  L01 - TOP w6: J3.10@893.84,395 Q8.3@985.43,395
NetJ11_50: J11.50 J12.2 | length 2020.2
  L05 - PWR w15: J12.2@4632,2956 4632,3011 4666,3045 4911,3045 5104,2852 5104,1598 v1(5094.59,1588.59)
  L08 - BOTTOM w10: J11.50@4962.8,1588.49 J11.50@4962.8,1588.49 5094.54,1588.54 v1(5094.59,1588.59)
NetJ16_9: J16.9 R186.2 | length 117.6
  L01 - TOP w4.3: J16.9@3840.43,3570.28 3840.43,3500.27 3845,3495.71 v1(3845,3492)
  L08 - BOTTOM w4.3: R186.2@3836.69,3526 3836.69,3504.02 3845,3495.71 v1(3845,3492)
NetJ17_1: J17.1 R192.1 U51.15 | length 926.8
  L08 - BOTTOM w4.3: U51.15@2871.76,2925.87 2841.78,2925.87 v1(2830.65,2937) 2850.48,2956.83 2850.48,3043.05 2930.43,3123 3150,3123 3226.9,3199.9 3287.15,3199.9 3425,3337.75 J17.1@3425,3408
NetL1_1: L1.1 U1.11 | length 94.3
  L01 - TOP w10: U1.11@3051.72,1443.1 3051.8,1443.18 3070.35,1443.18 3081.16,1454 3127.73,1454 3134.54,1460.81 L1.1@3134.54,1464.95
NetL2_1: L2.1 U1.23 | length 90.9
  L01 - TOP w10: L2.1@2837.13,1395.95 2840.77,1392.32 2892.06,1392.32 2903.39,1403.65 2921.72,1403.65 U1.23@2921.8,1403.73
NetL3_1: L3.1 U1.21 | length 89.6
  L01 - TOP w10: L3.1@2837.13,1451.95 2838.64,1453.46 2900,1453.46 2906.67,1446.79 2911.39,1446.79 2915.07,1443.1 U1.21@2921.8,1443.1
NetQ1_1: Q1.1 R11.1 | length 124.2
  L01 - TOP w6: v1(3057.5,1667) 3057.65,1666.85 3079.46,1666.85 Q1.1@3079.61,1666.7
  L08 - BOTTOM w6: R11.1@3036.5,1760.32 3036.5,1688 v1(3057.5,1667)
NetQ3_3: Q3.3 U14.5 | length 212.7
  L01 - TOP w10: U14.5@800,3265.51 800,3296 816.35,3296 v1(816.61,3296.26) ; Q3.3@812.61,3418.39 v1(812.61,3439.26)
  L08 - BOTTOM w10: v1(812.61,3439.26) 812.61,3437.1 816.61,3433.1 v1(816.61,3296.26)
NetQ4_3: Q4.3 U15.5 | length 168.2
  L01 - TOP w5: Q4.3@954.39,3047.61 1059.39,3047.61 1079.68,3027.31 U15.5@1079.68,2992.87
NetR8_1: R8.1 U6.4 U29.1 | length 87.2
  L01 - TOP w4.5: U6.4@3084.28,1172.28 3084.28,1175.59 3085.37,1176.68 v1(3126,1176.68)
  L08 - BOTTOM w4.5: U29.1@3086.35,1181.59 3121.09,1181.59 v1(3126,1176.68)
NetR15_2: R15.2 U7.16 | length 67.8
  L01 - TOP w4.5: U7.16@1609,510.76 1609,481 1618,472 1642.31,472 R15.2@1643,472.69
NetR18_1: R18.1 U8.8 | length 55.7
  L01 - TOP w6: R18.1@2257.11,1466.72 2263.95,1473.56 2277.41,1473.56 2289.9,1486.05 U8.8@2304.8,1486.05
NetR19_1: R19.1 U8.7 | length 50.6
  L01 - TOP w6: R19.1@2257.11,1498.72 2259.08,1498.72 2266.09,1505.73 U8.7@2304.8,1505.73
NetR20_1: R20.1 U8.12 | length 56
  L01 - TOP w6: U8.12@2383.54,1466.36 2383.54,1448.99 2392.39,1440.15 2392.39,1423.71 R20.1@2399.23,1416.87
NetR21_2: R21.2 U8.15 | length 52.4
  L01 - TOP w4.5: v1(2389.37,1524.91) 2389.62,1525.17 2402.98,1525.17 U8.15@2403.23,1525.42
  L08 - BOTTOM w4.5: R21.2@2372.06,1554.91 2374.02,1554.91 2381.62,1547.32 2381.62,1545.35 2386.79,1540.18 2386.79,1527.5 v1(2389.37,1524.91)
NetR22_2: R22.2 U8.2 | length 44.5
  L01 - TOP w6: U8.2@2363.86,1564.79 2363.86,1579.76 2369.68,1585.59 R22.2@2369.68,1606.91
NetR24_SOM-ETH1_2: R24_SOM-ETH1.2 R25_SOM-ETH1.2 U9_SOM-ETH1.1 | length 130.1
  L01 - TOP w4.3: R24_SOM-ETH1.2@1640.13,1548.76 1638.13,1546.76 v1(1638.13,1517.64) 1662.16,1493.61 U9_SOM-ETH1.1@1662.16,1461.38
  L08 - BOTTOM w4.3: v1(1638.13,1517.64) 1638.13,1546.76 R25_SOM-ETH1.2@1640.13,1548.76
NetR24_SOM-ETH2_2: R24_SOM-ETH2.2 R25_SOM-ETH2.2 U9_SOM-ETH2.1 | length 130.1
  L01 - TOP w4.3: R24_SOM-ETH2.2@1639.13,1105.76 1637.13,1103.76 v1(1637.13,1074.64) 1661.16,1050.61 U9_SOM-ETH2.1@1661.16,1018.38
  L08 - BOTTOM w4.3: v1(1637.13,1074.64) 1637.13,1103.76 R25_SOM-ETH2.2@1639.13,1105.76
NetR26_SOM-ETH1_2: R26_SOM-ETH1.2 U9_SOM-ETH1.10 | length 63.6
  L01 - TOP w7: R26_SOM-ETH1.2@1693.13,1240.32 1696.93,1244.12 1696.93,1262.63 1707.43,1273.14 U9_SOM-ETH1.10@1707.43,1297.99
NetR26_SOM-ETH2_2: R26_SOM-ETH2.2 U9_SOM-ETH2.10 | length 63.6
  L01 - TOP w7: R26_SOM-ETH2.2@1692.13,797.32 1695.93,801.12 1695.93,819.63 1706.43,830.14 U9_SOM-ETH2.10@1706.43,854.99
NetR45_1: R45.1 U10.D3 | length 161
  L01 - TOP w4.5: U10.D3@3014.93,966.69 3031.74,983.5 3125.5,983.5 3144,1002 3160.45,1002 R45.1@3161.09,1002.64
NetR46_1: R46.1 U10.D2 | length 156.3
  L01 - TOP w4.5: U10.D2@3014.93,927.32 3031.01,927.32 3049.33,909 3122,909 3128,915 3160.97,915 R46.1@3161.09,914.89
NetR47_1: R47.1 U10.C4 | length 195.3
  L01 - TOP w4.5: R47.1@2796.02,1000 2847,1000 2863,984 2942.64,984 2964.7,1006.06 U10.C4@2975.56,1006.06
NetR48_1: R48.1 U10.D4 | length 228.4
  L01 - TOP w4.5: R48.1@2796,1029 2865.6,1029 2870.7,1023.9 2997.09,1023.9 U10.D4@3014.93,1006.06
NetR49_1: R49.1 U10.D5 | length 228
  L01 - TOP w4.5: R49.1@2796.02,1057 2838.38,1057 2843.63,1062.25 2998.11,1062.25 v1(3014.93,1045.43)
NetR50_1: R50.1 U10.E3 | length 109.6
  L01 - TOP w4.5: U10.E3@3054.3,966.69 3083.69,966.69 3090,973 3160.7,973 R50.1@3161.09,973.39
NetR53_1: R53.1 U10.E2 | length 113.8
  L01 - TOP w4.5: U10.E2@3054.3,927.32 3079.32,927.32 3096,944 3160.95,944 R53.1@3161.09,944.14
NetR54_1: R54.1 U10.E1 | length 107.7
  L01 - TOP w4.5: U10.E1@3054.3,887.95 3055.46,886.8 3159.93,886.8 R54.1@3161.09,885.64
NetR55_1: R55.1 U11.1 | length 38.1
  L01 - TOP w4.5: U11.1@1978.5,2007.58 2012.21,2007.58 R55.1@2015.32,2010.68
NetR56_2: R56.2 U11.2 | length 44.5
  L01 - TOP w5: R56.2@1958.63,2052 1958.82,2051.81 U11.2@1958.82,2007.58
NetR57_2: R57.2 U11.3 | length 102.3
  L01 - TOP w8: U11.3@1939.13,2007.58 1939.13,2035.7 1932,2042.83 1932,2079.31 1936.69,2084 R57.2@1957.63,2084
NetR58_1: R58.1 R59.2 U12.2 | length 302.3
  L01 - TOP w15: v1(1821.09,3525.65) 1821.25,3525.5 1821.25,3492.81 R58.1@1821.41,3492.65
  L03 - SIG w15: v1(1592.53,3427.54) 1640.49,3475.5 1770.94,3475.5 v1(1821.09,3525.65)
NetR61_2: R61.2 U12.1 | length 66.5
  L01 - TOP w15: R61.2@1538.41,3492.65 1566.74,3492.65 1592.09,3467.3 U12.1@1592.09,3464.94
NetR74_2: R74.2 U16.D3 | length 173.3
  L01 - TOP w4.3: U16.D3@1698.37,1992.37 1698.37,1973.99 1721.18,1951.18 1721.18,1948.57 1732.26,1937.49 1734.87,1937.49 1752.58,1919.78 1752.58,1888.6 1743,1879.01 R74.2@1743,1847.05
NetR75_2: R75.2 U16.D2 | length 125.4
  L01 - TOP w4.3: R75.2@1685.67,1847.02 1685.67,1876.67 1715.52,1906.53 1715.52,1920.73 1698.37,1937.88 U16.D2@1698.37,1953
NetR76_2: R76.2 U16.C4 | length 114.1
  L01 - TOP w4.3: U16.C4@1659,2031.74 1659,2048.31 1673.84,2063.15 1673.84,2097.67 1672,2099.52 R76.2@1672,2138.98
NetR77_2: R77.2 U16.D4 | length 119.9
  L01 - TOP w4.3: U16.D4@1698.37,2031.74 1698.37,2050.12 1713.21,2064.96 1713.21,2122.4 1729,2138.19 R77.2@1729,2138.98
NetR78_2: R78.2 U16.D5 | length 68.7
  L01 - TOP w4.3: U16.D5@1698.37,2071.11 1699.44,2072.18 1699.44,2137.91 R78.2@1700.5,2138.98
NetR79_2: R79.2 U16.E3 | length 170.7
  L01 - TOP w4.3: U16.E3@1737.74,1992.37 1737.74,1973.99 1799,1912.73 R79.2@1799,1847.02
NetR80_2: R80.2 U16.E2 | length 119.6
  L01 - TOP w5: U16.E2@1737.74,1953 1770.67,1920.07 R80.2@1770.67,1847.02
NetR81_2: R81.2 U16.E1 | length 76
  L01 - TOP w4.3: R81.2@1715,1847.02 1716,1848.02 1716,1891.89 U16.E1@1737.74,1913.63
NetR82_2: R82.2 U16.C3 | length 160.5
  L01 - TOP w3.5: R82.2@1657.33,1847.02 1657.33,1874.26
  L01 - TOP w4.3: 1657.33,1874.26 1676.46,1893.39 1676.46,1956.53 1659,1973.99 U16.C3@1659,1992.37
NetR83_2: R83.2 U16.C2 | length 181.8
  L01 - TOP w4: R83.2@1592,1847.02 1592,1847.81 1604.32,1860.13 1604.32,1959.67 1612.34,1967.69 1627.66,1967.69 1642.35,1953 U16.C2@1659,1953
NetR96_2: R96.2 U22.1 | length 44.7
  L08 - BOTTOM w4.5: U22.1@392.8,2616.88 392.8,2574.89 R96.2@394.69,2573
NetR98_1: R98.1 SW2.2 SW2.4 | length 265.7
  L01 - TOP w8: v1(39.54,2434.76) SW2.4@39.54,2655.24
  L08 - BOTTOM w8: v1(39.54,2434.76) 58.97,2454.2 58.97,2463.69 R98.1@64.81,2469.54
NetR99_2: R99.2 U7.11 | length 68.1
  L01 - TOP w4.5: v1(1496,556) U7.11@1524.33,556.02
  L08 - BOTTOM w4.5: R99.2@1459,549.37 1485.72,549.37 1492.35,556 v1(1496,556)
NetR100_2: R100.2 U7.1 | length 86.2
  L01 - TOP w6: U7.1@1634.59,536.35 1641.68,536.35 1661,517.03 v1(1661,516)
  L08 - BOTTOM w6: R100.2@1643,472.69 1643,498 v1(1661,516)
NetR103_2: R103.2 U23.16 | length 43.7
  L08 - BOTTOM w6: R103.2@812,2405.69 812,2434.36 817.59,2439.95 U23.16@817.59,2447.04
NetR107_2: R107.2 U23.1 | length 77.4
  L08 - BOTTOM w6: R107.2@726,2447 727,2446 758.28,2446 784.91,2472.63 U23.1@792,2472.63
NetR108_1: R108.1 SW1.1 U23.2 | length 380.8
  L01 - TOP w6: v1(762,2488) 762,2421 794,2389 SW1.1@991,2389
  L08 - BOTTOM w8: R108.1@726,2479 750.29,2479 759.29,2488 v1(762,2488) 764.71,2488 769.02,2492.31 U23.2@792,2492.31
NetR109_1: R109.1 SW1.2 U23.3 | length 328.9
  L01 - TOP w6: v1(762.5,2515) 763,2515 839,2439 SW1.2@991,2439
  L08 - BOTTOM w8: R109.1@726,2511 755.79,2511 759.79,2515 v1(762.5,2515) 765.21,2515 768.19,2512.02 U23.3@792,2512
NetR110_1: R110.1 SW1.3 U23.4 | length 323.3
  L01 - TOP w6: v1(762,2544) 909,2544 953.98,2499.02 980.98,2499.02 SW1.3@991,2489
  L08 - BOTTOM w8: R110.1@726,2543 726.5,2543.5 761.5,2543.5 v1(762,2544) 763.91,2542.09 774.51,2542.09 784.91,2531.68 U23.4@792,2531.68
NetR111_1: R111.1 SW1.4 U23.5 | length 244.8
  L01 - TOP w6: v1(857,2607) 858,2606 875,2606 942,2539 SW1.4@991,2539
  L08 - BOTTOM w6: R111.1@817,2595 R111.1@817.59,2594.41 ; U23.5@817.59,2557.28 R111.1@817.59,2594.41 ; v1(857,2607) 853.75,2607 848.6,2601.84 825.02,2601.84 R111.1@817.59,2594.41
NetR112_1: R112.1 SW4.2 SW4.4 | length 281.4
  L01 - TOP w8: SW4.4@1228.76,40.54 SW4.2@1449.24,40.54 1454.46,35.32 R112.1@1508,35.32
NetR113_1: R113.1 SW5.2 SW5.4 | length 278.8
  L01 - TOP w8: R113.1@1578,34.32 1627.54,34.32 SW5.4@1633.76,40.54 SW5.2@1854.24,40.54
NetR114_2: R114.2 SW3.1 U24.1 | length 396.1
  L01 - TOP w6: SW3.1@701.68,2893 712.31,2893 729,2876.31 v1(729,2856)
  L08 - BOTTOM w6: R114.2@724.69,2891 724.69,2863.56 729,2859.25 v1(729,2856) ; v1@731.18,2853.82 v1(729,2856) ; U24.1@887.7,2695.4 887.7,2812.55 882.84,2817.41 877.87,2817.41 868.46,2808 828.54,2808 780.54,2856 v1(729,2856)
NetR115_2: R115.2 SW3.2 U24.2 | length 171.5
  L08 - BOTTOM w8: U24.2@862.11,2695.4 862.11,2662.89 877,2648 904,2648 v1(949,2693) R115.2@976.31,2693
NetR116_2: R116.2 SW3.4 U24.3 | length 231.6
  L01 - TOP w8: SW3.4@701.68,2693 741.05,2693 770.09,2722.04 770.09,2727.09 v1(772,2729)
  L08 - BOTTOM w8: v1(772,2729) 774.71,2729 777.68,2731.98 818.74,2731.98 836.52,2714.2 U24.3@836.52,2695.4 836.1,2694.98 836.1,2645.42 R116.2@835.69,2645 R116.2@836.19,2644.5
NetR117_2: R117.2 SW3.8 U24.5 | length 251.7
  L01 - TOP w6: v1(810.65,2907.02) 824.67,2893 SW3.8@996.95,2893
  L08 - BOTTOM w8: R117.2@810.37,2930 810.65,2929.72 810.65,2870.88 U24.5@810.93,2870.6
NetR128_2: R128.2 SW6.4 | length 73
  L01 - TOP w8: SW6.4@2307.36,237.57 2307.79,238 v1(2347.03,238)
  L08 - BOTTOM w8: R128.2@2314.69,236 2315.69,237 2346.03,237 v1(2347.03,238)
NetR129_2: R129.2 SW6.3 | length 73
  L01 - TOP w8: SW6.3@2307.36,187.57 2307.79,188 v1(2347.03,188)
  L08 - BOTTOM w8: R129.2@2314.69,186 2315.69,187 2346.03,187 v1(2347.03,188)
NetR130_2: R130.2 SW6.2 | length 73
  L01 - TOP w8: SW6.2@2307.36,137.57 2307.79,138 v1(2347.03,138)
  L08 - BOTTOM w8: R130.2@2314.69,136 2315.69,137 2346.03,137 v1(2347.03,138)
NetR131_2: R131.2 SW6.1 | length 73
  L01 - TOP w8: SW6.1@2307.36,87.57 2307.79,88 v1(2347.03,88)
  L08 - BOTTOM w8: R131.2@2314.69,86 2315.69,87 2346.03,87 v1(2347.03,88)
NetR133_1: R133.1 U34.7 | length 38.9
  L01 - TOP w4.3: R133.1@2456,3026.31 2456,3026.13 2463.69,3018.44 U34.7@2491.5,3018.44
NetR145_1: R145.1 U41.95 | length 94.3
  L08 - BOTTOM w4.3: R145.1@3302.35,3063.35 3306.65,3067.65 U41.95@3394.86,3067.65
NetR149_2: R149.2 U41.4 | length 89.2
  L08 - BOTTOM w6: U41.4@4001.16,3036.15 4071.2,3036.15 4083.35,3024 R149.2@4085.31,3024
NetR150_2: R150.2 U41.3 | length 87.4
  L08 - BOTTOM w6: U41.3@4001.16,3051.9 4079.9,3051.9 R150.2@4086,3058
NetR154_2: R154.2 R161.2 U41.63 | length 140.8
  L01 - TOP w4.3: v1(3437,2477) 3437,2444.37 R161.2@3438,2443.37
  L08 - BOTTOM w4.3: R154.2@3438,2443.37 3437,2444.37 v1(3437,2477) 3466,2506 3466,2507.9 3469.66,2511.56 U41.63@3469.66,2536.15
NetR155_2: R155.2 R160.2 U41.62 | length 134
  L01 - TOP w4.3: v1(3469,2477) 3469,2444.37 R160.2@3470,2443.37
  L08 - BOTTOM w4.3: R155.2@3470,2443.37 3469,2444.37 v1(3469,2477) 3485.41,2493.41 U41.62@3485.41,2536.15
NetR156_2: R156.2 R159.2 U41.61 | length 126.7
  L01 - TOP w4.3: v1(3501,2477) 3501,2444.69 R159.2@3502,2443.69
  L08 - BOTTOM w4.3: U41.61@3501.16,2536.15 3501.11,2536.1 3501.11,2477.11 v1(3501,2477) 3501,2444.69 R156.2@3502,2443.69
NetR157_2: R157.2 R158.2 U41.60 | length 133.3
  L01 - TOP w5: v1(3533,2477) 3533,2444.69 R158.2@3534,2443.69
  L08 - BOTTOM w5: U41.60@3516.91,2536.15 3516.91,2493.09 v1(3533,2477) 3533,2444.69 R157.2@3534,2443.69
NetR164_2: R164.2 U41.70 | length 110.1
  L08 - BOTTOM w4.3: R164.2@3287.99,2681.7 3318.3,2681.7 3326.06,2673.94 U41.70@3394.86,2673.94
NetR167_2: R167.2 U41.59 | length 107.6
  L01 - TOP w4.3: v1(3565,2477) 3565,2444.69 R167.2@3566,2443.69
  L08 - BOTTOM w4.3: U41.59@3532.66,2536.15 3533.34,2535.47 3533.34,2506.45 3562.79,2477 v1(3565,2477)
NetR169_2: R169.2 U11.7 | length 53.6
  L01 - TOP w8: U11.7@1958.82,1891.42 1959.11,1891.13 1959.11,1841.52 R169.2@1961.63,1839
NetR172_1: R172.1 U32.4 U32.5 | length 83.6
  L01 - TOP w6: R172.1@1661.92,188.65 1695.99,188.65 1698.45,191.11 ; U32.4@1710.37,203.03 1703.07,203.03 1702.13,202.09 1702.13,194.79 1698.45,191.11 ; U32.5@1718.24,179.41 1717.31,180.35 1717.31,180.73 1708.82,180.73 1698.45,191.11
NetR182_2: R182.2 U2.N2 | length 100.4
  L01 - TOP w3.5: U2.N2@2640.27,1135.59 2652.84,1148.17 2685.54,1148.17
  L01 - TOP w4.3: 2685.54,1148.17 2687.92,1145.79 2704.82,1145.79 2715.61,1135 R182.2@2729.98,1135
NetR183_1: R183.1 U2.B7 | length 108.4
  L01 - TOP w3.5: R183.1@2490.58,756.02 2495.13,761.36 2495.13,768.94 2501.65,775.45 2501.65,803.75 2499.74,805.67 2499.74,841.52 U2.B7@2512.31,854.09
NetR184_2: R184.2 U2.N1 | length 76
  L01 - TOP w4.3: U2.N1@2665.86,1135.59 2700.6,1135.59 2729.19,1107 R184.2@2729.98,1107
NetR185_2: R185.2 U2.W20 | length 86.7
  L01 - TOP w4.3: R185.2@2093.02,1289 2093.09,1289.07 U2.W20@2179.64,1289.13 U2.W20@2179.64,1289.13
NetR194_2: R194.2 R195.1 U1.1 | length 138.3
  L01 - TOP w8: R194.2@2905.13,1308.64 2900.5,1304 v1(2876,1304) 2877.91,1305.91 2877.91,1314.57 v1(2923.77,1360.43)
  L08 - BOTTOM w8: v1(2876,1304) 2878.71,1304 2883.34,1308.64 R195.1@2905.13,1308.64
NetR196_1: R196.1 R197.1 U1.16 | length 56.7
  L01 - TOP w8: U1.16@2986.76,1488.38 2986.95,1488.56 2986.95,1544.77 v1(2987.13,1544.95)
NetR198_1: R198.1 U8.11 | length 50.9
  L01 - TOP w6: U8.11@2363.86,1466.36 2363.86,1420.24 R198.1@2367.23,1416.87
NetR198_2: R198.2 TP1.1
  other v1: 2367.23,1375.53
NetR199_1: R199.1 U8.6 | length 49.5
  L01 - TOP w6: R199.1@2257.4,1530.42 2262.4,1525.42 U8.6@2304.8,1525.42
NetR200_1: R200.1 U8.9 | length 58.2
  L01 - TOP w6: R200.1@2303.37,1416.91 2310.21,1423.76 2310.21,1437.55 2324.49,1451.83 U8.9@2324.49,1466.36
NetR208_1: R208.1 U2.P20 | length 89
  L01 - TOP w3.5: R208.1@2093.02,1167 2134.7,1167 2140.52,1161.18 U2.P20@2179.64,1161.18
NetR209_1: R209.1 U2.P19 | length 130
  L01 - TOP w3.94: R209.1@2093.02,1204 2112.02,1204 2142.05,1173.98 2184.94,1173.98 2192.41,1174 U2.P19@2205.23,1161.18
NetR210_1: R210.1 U2.K20 | length 85.3
  L01 - TOP w4.3: R210.1@2101,1075 2112.81,1075 2128.99,1058.82 U2.K20@2179.64,1058.82
NetR211_1: R211.1 U2.L19 | length 125.4
  L01 - TOP w3.5: R211.1@2100.02,1103 2100.81,1103 2134.46,1069.35 2166.9,1069.35 2169.38,1071.83 2192.65,1071.83 U2.L19@2205.23,1084.41
NetR212_2: R212.2 U2.E5 | length 164.7
  L01 - TOP w3.5: U2.E5@2563.5,930.87 2589.87,930.87 2628.03,969.03 2708.68,969.03 R212.2@2711.31,971.66
NetR215_1: R215.1 U20.4 | length 72.5
  L01 - TOP w8: U20.4@1355.92,270.28 1379.59,270.28 1402.8,247.07 1417.95,247.07 R215.1@1418.55,246.46
NetR218_2: R218.2 U2.B8 | length 108
  L01 - TOP w3.5: R218.2@2462.1,756.02 2462.1,786.83 2467.36,792.08 2467.36,800.9 2473.04,806.58 2473.43,810.61 cw(c2490,809) 2473.5,811.22 2473.71,812.8 2473.71,841.08 U2.B8@2486.72,854.09
NetR222_1: R222.1 U50.5 | length 49.2
  L01 - TOP w8: U50.5@3433.36,261 3450.13,261 3456.32,267.19 R222.1@3480,267.19
NetR223_2: R223.2 U41.35 | length 93.8
  L08 - BOTTOM w6: U41.35@3910.61,2536.15 3910.61,2504.39 3940,2475 R223.2@3940,2454.5
NetR224_2: R224.2 U41.36 | length 87.1
  L08 - BOTTOM w6: U41.36@3894.86,2536.15 3894.86,2501.14 3908,2488 R224.2@3908,2454.5
NetR225_2: R225.2 U41.38 | length 88
  L08 - BOTTOM w6: U41.38@3863.36,2536.15 3863.36,2512.02 3862,2510.66 3862,2481.54 3869.16,2474.39 3869.16,2461.34 R225.2@3876,2454.5
NetR226_2: R226.2 U43.2 | length 52.3
  L08 - BOTTOM w4.3: U43.2@4005,2016.91 4005,1965.99 R226.2@4006,1964.99
NetR227_1: R227.1 U2.A6 | length 87.5
  L01 - TOP w3.5: R227.1@2520,756.02 2520,756.81 2547.05,783.86 2547.05,807.79 2538.48,816.36 2538.48,827.93 U2.A6@2537.91,828.5
NetR228_1: R228.1 U2.B6 | length 109.7
  L01 - TOP w3.5: U2.B6@2537.91,854.09 2550.48,841.52 2550.48,817.65 2556.45,811.68 2556.45,776.34 2556.45,764.47 2553.34,761.36 2552.55,761.36 2548,756.81 R228.1@2548,756.02
NetR229_1: R229.1 U2.A5 | length 77.7
  L01 - TOP w3.5: U2.A5@2563.5,828.5 2563.5,825.72 2567.11,822.11 2567.11,817.6 2576.03,808.67 2576.03,776.34 R229.1@2576.03,756.02
NetR230_1: R230.1 U2.B5 | length 115.1
  L01 - TOP w3.5: U2.B5@2563.5,854.09 2576.51,841.08 2576.51,821.49 2592,806 2592,776.34 2592,768.54 R230.1@2604.52,756.02
NetR231_1: R231.1 U2.A4 | length 90.7
  L01 - TOP w4.3: U2.A4@2589.09,828.5 2604.43,813.16 2604.43,784.59 2612.69,776.34 2614.9,774.12 R231.1@2633,756.02
NetR232_2: R232.2 U2.U19 | length 121.4
  L01 - TOP w3.5: R232.2@2093.02,1234 2093.81,1234 2098.36,1229.45 2098.36,1228.67 2101.65,1225.37 2127.47,1225.37 2192.65,1225.37 U2.U19@2205.23,1237.95
NetR234_1: R234.1 U2.F17 | length 186.8
  L01 - TOP w4.5: R234.1@2090.82,943.42 2094.4,947 v1(2094.4,953.5)
  L06 - SIG w4.5: v1(2094.4,953.5) 2162.26,953.5 2175.75,940 2240,940 v1(2257,957)
NetR235_1: R235.1 U2.D20 | length 95.8
  L01 - TOP w5: R235.1@2093.02,916 2093.81,916 2110.31,899.5 2127.47,899.5 2161.85,899.5 2167.63,905.28 U2.D20@2179.64,905.28
NetR236_1: R236.1 U2.C20 | length 89.6
  L01 - TOP w3.5: R236.1@2093.02,887 2126,887 2133.31,879.69 U2.C20@2179.64,879.69
NetR237_1: R237.1 U2.D19 | length 142.2
  L01 - TOP w3.5: R237.1@2093.02,858 2113,858 2121.67,866.67 2127.47,866.67 2184.41,866.67 2192.65,874.91 2192.65,892.7 U2.D19@2205.23,905.28
NetR238_1: R238.1 U2.D17 | length 171.1
  L01 - TOP w4.3: R238.1@2262.72,755.66 2262.86,755.8 2262.86,777.86 v1(2263,778)
  L08 - BOTTOM w4.5: v1(2256.43,905.3) 2256.43,904.18 2233.95,881.7 2233.95,814.3 2247.15,801.1 2247.15,793.85 v1(2263,778)
NetTP6_1: TP6.1 U7.2 | length 72.2
  L01 - TOP w4.5: U7.2@1634.59,556.04 1635.07,556.52 1662.3,556.52 1675.82,543 TP6.1@1701,543
NetTP7_1: TP7.1 U23.9 | length 79.1
  L08 - BOTTOM w6: U23.9@902.24,2531.68 902.24,2553.24 921,2572 928,2572 TP7.1@945,2589
NetTP8_1: TP8.1 U33.9 | length 34.6
  L01 - TOP w4.3: U33.9@2336.53,2999.38 2336.72,2999.19 2370.81,2999.19 TP8.1@2371,2999
NetTP9_1: TP9.1 U33.5 | length 74.4
  L01 - TOP w4.3: TP9.1@2205,3016 2205.44,3015.56 2277.04,3015.56 U33.5@2277.47,3015.13 U33.5@2276.35,3014
NetTP15_1: TP15.1 U41.49 | length 80.6
  L08 - BOTTOM w6: U41.49@3690.14,2536.15 3690.14,2476.01 3701,2465.14 TP15.1@3701,2460
NetTP16_1: TP16.1 U41.50 | length 80.9
  L08 - BOTTOM w6: TP16.1@3663,2460 3663,2465.14 3674.39,2476.53 U41.50@3674.39,2536.15
NetTP17_1: TP17.1 U41.81 | length 142.1
  L08 - BOTTOM w4.3: TP17.1@3267,2872 3271.25,2872 3300.9,2842.35 3322.55,2842.35 3327.38,2847.17 U41.81@3394.86,2847.17
NetTP18_1: TP18.1 U41.82 | length 80.9
  L08 - BOTTOM w4.3: TP18.1@3314,2863 TP18.1@3314,2863 3394.82,2862.96 U41.82@3394.86,2862.92
NetTP19_1: TP19.1 U41.78 | length 191.6
  L08 - BOTTOM w4.3: TP19.1@3207,2809 3324.77,2809 3333.84,2799.93 U41.78@3394.86,2799.93
NetTP20_1: TP20.1 U41.77 | length 184.2
  L08 - BOTTOM w4.3: TP20.1@3226,2772 3250.65,2796.65 3322.55,2796.65 3335.02,2784.18 U41.77@3394.86,2784.18
NetTP21_1: TP21.1 U41.76 | length 84
  L08 - BOTTOM w4.3: TP21.1@3314,2776 3319.6,2776 3327.17,2768.43 U41.76@3394.86,2768.43
NetTP22_1: TP22.1 U41.75 | length 135.2
  L08 - BOTTOM w4.3: TP22.1@3267.68,2772 3284.33,2755.35 3323.85,2755.35 3326.52,2752.69 U41.75@3394.86,2752.69
NetTP23_1: TP23.1 U41.74 | length 248.3
  L08 - BOTTOM w4.3: TP23.1@3168,2790 TP23.1@3169,2789 ; TP23.1@3170,2790 3214.95,2745.05 3313.22,2745.05 3321.33,2736.94 U41.74@3394.86,2736.94
NetTP24_1: TP24.1 U41.73 | length 237.6
  L08 - BOTTOM w4.3: TP24.1@3170,2752 3187.39,2734.61 3309.08,2734.61 3322.51,2721.19 U41.73@3394.86,2721.19
NetTP25_1: TP25.1 U41.72 | length 230.4
  L08 - BOTTOM w4.3: TP25.1@3168,2714 3315.13,2714 3323.69,2705.44 U41.72@3394.86,2705.44
NetTP26_1: TP26.1 U41.71 | length 242.8
  L08 - BOTTOM w4.3: TP26.1@3170,2673 3200,2703 3311.57,2703 3324.87,2689.69 U41.71@3394.86,2689.69
NetTP29_1: TP29.1 U7.7 | length 53.7
  L01 - TOP w4.5: TP29.1@1562,671 1562,665.45 1570.31,657.14 1570.31,621.68 U7.7@1569.63,621
NetTP30_1: TP30.1 U23.10 | length 74.1
  L08 - BOTTOM w6: U23.10@902.24,2512 936,2512 944,2520 TP30.1@944,2549
NetTP32_1: TP32.1 U1.5 | length 75.2
  L01 - TOP w8: U1.5@3006.45,1358.46 3006.45,1332.44 3023.44,1315.45 3023.44,1292.65 TP32.1@3025.13,1290.95
NetTP33_1: TP33.1 U1.3 | length 69.5
  L01 - TOP w8: TP33.1@2950.13,1295.95 2953.39,1299.21 2953.39,1320.38 2967.08,1334.07 U1.3@2967.08,1358.46
NetU20_2: U20.2 U48.4 | length 52.5
  L01 - TOP w8: U20.2@1336.24,246.65 1338.14,244.75 1338.14,238.83 1355.92,221.05 U48.4@1355.92,202.28
OSPI0_CLK: R36.1 R52.2 R184.1 U10.B2 | length 515.4
  L01 - TOP w4.3: R184.1@2752.02,1107 v1(2780,1107) ; v1(2901.02,842.19) 2901.02,892.15 U10.B2@2936.19,927.32
  L01 - TOP w8: R36.1@2904.47,804.32 v1@2904.47,836.03
  L08 - BOTTOM w4.3: v1(2780,1107) 2783,1107 2826,1064 2826,917.2 v1(2901.02,842.19)
  L08 - BOTTOM w8: v1(2901.02,842.19) 2901.02,839.48 2904.47,836.03 R52.2@2904.47,804.32
OSPI0_CSN0: R34.1 U2.L2 U10.C2 | length 627.3
  L01 - TOP w4.3: v1(2933.68,842.19) 2933.68,807.44 R34.1@2936.8,804.32
  L01 - TOP w4.5: v1(2933.68,842.19) 2921.25,854.63 2921.25,894.14 2936.99,909.88 2958.12,909.88 U10.C2@2975.56,927.32
  L03 - SIG w4.5: v1(2857,837) 2879.34,859.34 2916.53,859.34 v1(2933.68,842.19)
  L08 - BOTTOM w4.3: v1(2640.27,1084.41) 2664.38,1084.41 2722.34,1026.45 2722.34,939.79 2825.12,837 v1(2857,837)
